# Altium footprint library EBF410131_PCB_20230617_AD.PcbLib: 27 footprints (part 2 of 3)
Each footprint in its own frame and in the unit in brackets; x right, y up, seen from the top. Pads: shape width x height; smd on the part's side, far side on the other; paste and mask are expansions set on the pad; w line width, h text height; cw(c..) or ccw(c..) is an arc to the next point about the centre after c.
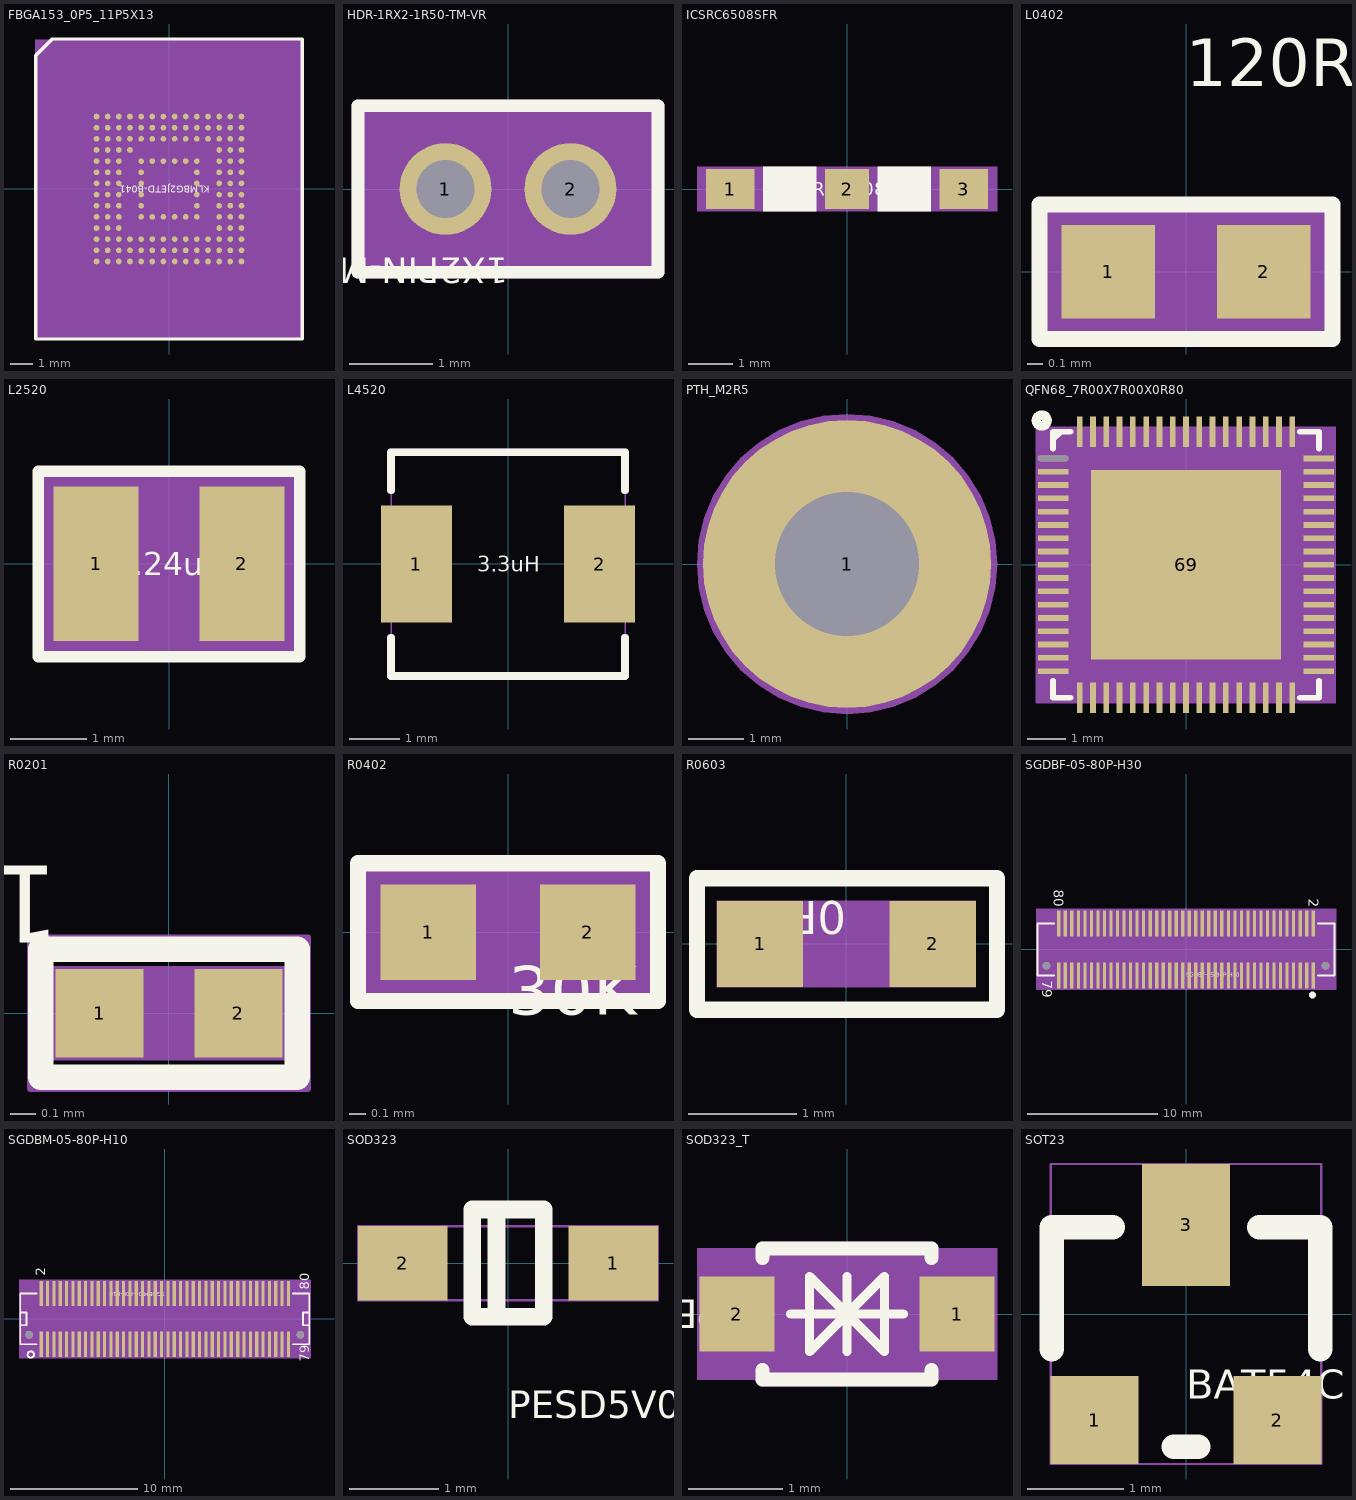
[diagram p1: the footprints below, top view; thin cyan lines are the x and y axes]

## FBGA153_0P5_11P5X13 [mil] "FBGA153_0P5_11P5X13"
pads (153):
  round 10 smd: A1(-127.95,127.95) A2(-108.27,127.95) A3(-88.58,127.95) A4(-68.9,127.95) A5(-49.21,127.95) A6(-29.53,127.95) A7(-9.84,127.95) A8(9.84,127.95) A9(29.53,127.95) A10(49.21,127.95) A11(68.9,127.95) A12(88.58,127.95) A13(108.27,127.95) A14(127.95,127.95) B1(-127.95,108.27) B2(-108.27,108.27) B3(-88.58,108.27) B4(-68.9,108.27) B5(-49.21,108.27) B6(-29.53,108.27) B7(-9.84,108.27) B8(9.84,108.27) B9(29.53,108.27) B10(49.21,108.27) B11(68.9,108.27) B12(88.58,108.27) B13(108.27,108.27) B14(127.95,108.27) C1(-127.95,88.58) C2(-108.27,88.58) C3(-88.58,88.58) C4(-68.9,88.58) C5(-49.21,88.58) C6(-29.53,88.58) C7(-9.84,88.58) C8(9.84,88.58) C9(29.53,88.58) C10(49.21,88.58) C11(68.9,88.58) C12(88.58,88.58) C13(108.27,88.58) C14(127.95,88.58) D1(-127.95,68.9) D2(-108.27,68.9) D3(-88.58,68.9) D4(-68.9,68.9) D12(88.58,68.9) D13(108.27,68.9) D14(127.95,68.9) E1(-127.95,49.21) E2(-108.27,49.21) E3(-88.58,49.21) E5(-49.21,49.21) E6(-29.53,49.21) E7(-9.84,49.21) E8(9.84,49.21) E9(29.53,49.21) E10(49.21,49.21) E12(88.58,49.21) E13(108.27,49.21) E14(127.95,49.21) F1(-127.95,29.53) F2(-108.27,29.53) F3(-88.58,29.53) F5(-49.21,29.53) F10(49.21,29.53) F12(88.58,29.53) F13(108.27,29.53) F14(127.95,29.53) G1(-127.95,9.84) G2(-108.27,9.84) G3(-88.58,9.84) G5(-49.21,9.84) G10(49.21,9.84) G12(88.58,9.84) G13(108.27,9.84) G14(127.95,9.84) H1(-127.95,-9.84) H2(-108.27,-9.84) H3(-88.58,-9.84) H5(-49.21,-9.84) H10(49.21,-9.84) H12(88.58,-9.84) H13(108.27,-9.84) H14(127.95,-9.84) J1(-127.95,-29.53) J2(-108.27,-29.53) J3(-88.58,-29.53) J5(-49.21,-29.53) J10(49.21,-29.53) J12(88.58,-29.53) J13(108.27,-29.53) J14(127.95,-29.53) K1(-127.95,-49.21) K2(-108.27,-49.21) K3(-88.58,-49.21) K5(-49.21,-49.21) K6(-29.53,-49.21) K7(-9.84,-49.21) K8(9.84,-49.21) K9(29.53,-49.21) K10(49.21,-49.21) K12(88.58,-49.21) K13(108.27,-49.21) K14(127.95,-49.21) L1(-127.95,-68.9) L2(-108.27,-68.9) L3(-88.58,-68.9) L12(88.58,-68.9) L13(108.27,-68.9) L14(127.95,-68.9) M1(-127.95,-88.58) M2(-108.27,-88.58) M3(-88.58,-88.58) M4(-68.9,-88.58) M5(-49.21,-88.58) M6(-29.53,-88.58) M7(-9.84,-88.58) M8(9.84,-88.58) M9(29.53,-88.58) M10(49.21,-88.58) M11(68.9,-88.58) M12(88.58,-88.58) M13(108.27,-88.58) M14(127.95,-88.58) N1(-127.95,-108.27) N2(-108.27,-108.27) N3(-88.58,-108.27) N4(-68.9,-108.27) N5(-49.21,-108.27) N6(-29.53,-108.27) N7(-9.84,-108.27) N8(9.84,-108.27) N9(29.53,-108.27) N10(49.21,-108.27) N11(68.9,-108.27) N12(88.58,-108.27) N13(108.27,-108.27) N14(127.95,-108.27) P1(-127.95,-127.95) P2(-108.27,-127.95) P3(-88.58,-127.95) P4(-68.9,-127.95) P5(-49.21,-127.95) P6(-29.53,-127.95) P7(-9.84,-127.95) P8(9.84,-127.95) P9(29.53,-127.95) P10(49.21,-127.95) P11(68.9,-127.95) P12(88.58,-127.95) P13(108.27,-127.95) P14(127.95,-127.95)
Top Overlay:
  lines w6: -235.35,-264.87 -235.35,235.77 -206.24,264.87 235.35,264.87 235.35,-264.87 -235.35,-264.87
  text "KLMBG2JETD-B041" at 72,6 h12
Top 3D Body:
  region: -236.22,-263.78 236.22,-263.78 236.22,263.78 -236.22,263.78
Top Component Center:
  lines w1: -10,0 10,0 ; 0,-10 0,10
Mechanical 12:
  text "E9" at 37.53,49.21 h10
  text "E10" at 61.21,49.21 h10
  text "F10" at 61.21,29.53 h10
  text "K10" at 61.21,-49.21 h10
  text "A1" at -119.95,127.95 h10
  text "A10" at 61.21,127.95 h10
  text "H2" at -100.27,-9.84 h10
  text "H3" at -80.58,-9.84 h10
  text "A11" at 80.9,127.95 h10
  text "H12" at 100.58,-9.84 h10
  text "H13" at 120.27,-9.84 h10
  text "H14" at 139.95,-9.84 h10
  text "J1" at -119.95,-29.53 h10
  text "J2" at -100.27,-29.53 h10
  text "J3" at -80.58,-29.53 h10
  text "A12" at 100.58,127.95 h10
  text "J12" at 100.58,-29.53 h10
  text "J13" at 120.27,-29.53 h10
  text "J14" at 139.95,-29.53 h10
  text "K1" at -119.95,-49.21 h10
  text "K2" at -100.27,-49.21 h10
  text "K3" at -80.58,-49.21 h10
  text "A13" at 120.27,127.95 h10
  text "K12" at 100.58,-49.21 h10
  text "K13" at 120.27,-49.21 h10
  text "A14" at 139.95,127.95 h10
  text "K14" at 139.95,-49.21 h10
  text "L1" at -119.95,-68.9 h10
  text "L2" at -100.27,-68.9 h10
  text "L3" at -80.58,-68.9 h10
  text "B1" at -119.95,108.27 h10
  text "L12" at 100.58,-68.9 h10
  text "L13" at 120.27,-68.9 h10
  text "L14" at 139.95,-68.9 h10
  text "M1" at -119.95,-88.58 h10
  text "M2" at -100.27,-88.58 h10
  text "M3" at -80.58,-88.58 h10
  text "M7" at -1.84,-88.58 h10
  text "M8" at 17.84,-88.58 h10
  text "M9" at 37.53,-88.58 h10
  text "M10" at 61.21,-88.58 h10
  text "M11" at 80.9,-88.58 h10
  text "M12" at 100.58,-88.58 h10
  text "M13" at 120.27,-88.58 h10
  text "M14" at 139.95,-88.58 h10
  text "N1" at -119.95,-108.27 h10
  text "N3" at -80.58,-108.27 h10
  text "N6" at -21.53,-108.27 h10
  text "N7" at -1.84,-108.27 h10
  text "N8" at 17.84,-108.27 h10
  text "N9" at 37.53,-108.27 h10
  text "N10" at 61.21,-108.27 h10
  text "N11" at 80.9,-108.27 h10
  text "N12" at 100.58,-108.27 h10
  text "N13" at 120.27,-108.27 h10
  text "N14" at 139.95,-108.27 h10
  text "P1" at -119.95,-127.95 h10
  text "P2" at -100.27,-127.95 h10
  text "P8" at 17.84,-127.95 h10
  text "P9" at 37.53,-127.95 h10
  text "P11" at 80.9,-127.95 h10
  text "P12" at 100.58,-127.95 h10
  text "P13" at 120.27,-127.95 h10
  text "P14" at 139.95,-127.95 h10
  text "A2" at -100.27,127.95 h10
  text "B7" at -1.84,108.27 h10
  text "B8" at 17.84,108.27 h10
  text "B9" at 37.53,108.27 h10
  text "B10" at 61.21,108.27 h10
  text "B11" at 80.9,108.27 h10
  text "B12" at 100.58,108.27 h10
  text "B13" at 120.27,108.27 h10
  text "B14" at 139.95,108.27 h10
  text "C1" at -119.95,88.58 h10
  text "C3" at -80.58,88.58 h10
  text "C5" at -41.21,88.58 h10
  text "C7" at -1.84,88.58 h10
  text "C8" at 17.84,88.58 h10
  text "C9" at 37.53,88.58 h10
  text "C10" at 61.21,88.58 h10
  text "C11" at 80.9,88.58 h10
  text "C12" at 100.58,88.58 h10
  text "C13" at 120.27,88.58 h10
  text "C14" at 139.95,88.58 h10
  text "D1" at -119.95,68.9 h10
  text "D2" at -100.27,68.9 h10
  text "D3" at -80.58,68.9 h10
  text "D4" at -60.9,68.9 h10
  text "D12" at 100.58,68.9 h10
  text "D13" at 120.27,68.9 h10
  text "D14" at 139.95,68.9 h10
  text "E1" at -119.95,49.21 h10
  text "E2" at -100.27,49.21 h10
  text "E3" at -80.58,49.21 h10
  text "E12" at 100.58,49.21 h10
  text "E13" at 120.27,49.21 h10
  text "E14" at 139.95,49.21 h10
  text "F1" at -119.95,29.53 h10
  text "F2" at -100.27,29.53 h10
  text "F3" at -80.58,29.53 h10
  text "A8" at 17.84,127.95 h10
  text "F12" at 100.58,29.53 h10
  text "F13" at 120.27,29.53 h10
  text "F14" at 139.95,29.53 h10
  text "G1" at -119.95,9.84 h10
  text "G2" at -100.27,9.84 h10
  text "A9" at 37.53,127.95 h10
  text "G12" at 100.58,9.84 h10
  text "G13" at 120.27,9.84 h10
  text "G14" at 139.95,9.84 h10
  text "H1" at -119.95,-9.84 h10
  text "A7" at -1.84,127.95 h10
  text "E5" at -41.21,49.21 h10
  text "E8" at 17.84,49.21 h10
  text "G3" at -80.58,9.84 h10
  text "G10" at 61.21,9.84 h10
  text "K6" at -21.53,-49.21 h10
  text "K7" at -1.84,-49.21 h10
  text "P7" at -1.84,-127.95 h10
  text "P10" at 61.21,-127.95 h10
  text "K5" at -41.21,-49.21 h10
  text "C2" at -100.27,88.58 h10
  text "M4" at -60.9,-88.58 h10
  text "N4" at -60.9,-108.27 h10
  text "P5" at -41.21,-127.95 h10
  text "P3" at -80.58,-127.95 h10
  text "C6" at -21.53,88.58 h10
  text "J10" at 61.21,-29.53 h10
  text "K9" at 37.53,-49.21 h10
  text "F5" at -41.21,29.53 h10
  text "E6" at -21.53,49.21 h10
  text "P4" at -60.9,-127.95 h10
  text "N5" at -41.21,-108.27 h10
  text "P6" at -21.53,-127.95 h10
  text "N2" at -100.27,-108.27 h10
  text "A6" at -21.53,127.95 h10
  text "K8" at 17.84,-49.21 h10
  text "H10" at 61.21,-9.84 h10
  text "E7" at -1.84,49.21 h10
  text "C4" at -60.9,88.58 h10
  text "J5" at -41.21,-29.53 h10
  text "G5" at -41.21,9.84 h10
  text "A3" at -80.58,127.95 h10
  text "A4" at -60.9,127.95 h10
  text "A5" at -41.21,127.95 h10
  text "B2" at -100.27,108.27 h10
  text "B3" at -80.58,108.27 h10
  text "B4" at -60.9,108.27 h10
  text "B5" at -41.21,108.27 h10
  text "B6" at -21.53,108.27 h10
  text "M5" at -41.21,-88.58 h10
  text "M6" at -21.53,-88.58 h10
  text "H5" at -41.21,-9.84 h10
Top Assembly:
  circle w6: c-188.98,220.47 r26.41
  lines w6: -228.35,-257.87 -228.35,232.87 -203.35,257.87 228.35,257.87 228.35,-257.87 -228.35,-257.87
3D body: height 150, standoff 0, extent -236.22,-263.78 236.22,263.78

## HDR-1RX2-1R50-TM-VR [mm] "HDR-1RX2-1R50-TM-VR"
pads (2):
  round 1.1 hole 0.7: 1(-0.75,0) 2(0.75,0)
Top Overlay:
  lines w0.15: -1.8,-1 -1.8,1 1.8,1 1.8,-1 -1.8,-1
  text "1X2PIN-M" at 0,-0.823 h0.3
Top 3D Body:
  region: -1.8,1 -1.8,-1 1.8,-1 1.8,1
Mechanical 12:
  text "2" at 0.75,-0.254 h0.64
  text "1" at -0.75,-0.254 h0.64
Top Assembly:
  lines w0.15: -1.8,-1 -0.8,-1 1.8,-1 1.8,1 -1.8,1 -1.8,-1
3D body: height 3.81, standoff 0, extent -1.8,-1 1.8,1

## ICSRC6508SFR [mm] "ICSRC6508SFR"
pads (3):
  rect 1.1x0.9 smd: 1(-2.65,0) 3(2.65,0)
  rect 1x0.9 smd: 2(0,0)
Top Overlay:
  dashed: -1.9,0.5 -1.9,-0.5 -0.7,-0.5 -0.7,0.5
  dashed: 0.7,0.5 0.7,-0.5 1.9,-0.5 1.9,0.5
  text "ICSRC6508SFR" at -1.463,-0.152 h0.3
Top 3D Body:
  region: 3.4,-0.5 3.4,0.5 -3.4,0.5 -3.4,-0.5
Mechanical 12:
  text "1" at -2.904,0 h0.64
  text "3" at 2.396,0 h0.64
  text "2" at -0.254,0 h0.64
Top Assembly:
  lines w0.1: -3.35,-0.45 3.35,-0.45 3.35,0.45 -3.35,0.45 -3.35,-0.45
3D body: height 3.81, standoff 0, extent -3.4,-0.5 3.4,0.5

## L0402 [mm] "L0402"
pads (2):
  rect 0.599x0.599 smd: 1(-0.5,0) 2(0.5,0)
Top Overlay:
  lines w0.102: -0.94,-0.432 -0.94,0.432 0.94,0.432 0.94,-0.432 -0.94,-0.432
  text "120R 100MHz" at 0,1.189 h0.3
Top 3D Body:
  region: 0.94,0.432 0.94,-0.432 -0.94,-0.432 -0.94,0.432
Mechanical 12:
  text "1" at -0.5,0.254 h0.64
  text "2" at 0.5,0.254 h0.64
Top Assembly:
  dashed: -0.94,-0.432 -0.94,0.432 0.94,0.432 0.94,-0.432
3D body: height 3.81, standoff 0, extent -0.94,-0.432 0.94,0.432

## L2520 [mil] "L2520"
pads (2):
  rect 44x80 smd: 1(-37.75,0) 2(37.75,0)
Top Overlay:
  lines w6: -67.68,-48.15 -67.68,47.92 67.67,47.92 67.67,-48.15 -67.67,-48.15 -67.68,-48.15
  text "0.24uH" at -28.8,-6 h12
Top 3D Body:
  region: -65,-45 65,-45 65,45 -65,45
Mechanical 12:
  text "1" at -42.47,0 h11.81
  text "2" at 33.02,0 h11.81
3D body: height 150, standoff 0, extent -65,-45 65,45

## L4520 [mm] "L4520"
pads (2):
  rect 1.4x2.3 smd: 1(-1.803,-0.003) 2(1.798,-0.003)
Top Overlay:
  lines w0.15: -2.303,-1.452 -2.303,-2.203 2.298,-2.203 2.298,-1.452 ; -2.303,1.447 -2.303,2.198 2.298,2.198 2.298,1.447
  text "3.3uH" at -0.61,-0.152 h0.3
Top 3D Body:
  lines w0.025: -2.303,-2.203 -2.303,2.202 2.303,2.202 2.303,-2.203 -2.303,-2.203
Mechanical 12:
  text "2" at 1.544,-0.003 h0.64
  text "1" at -2.057,-0.003 h0.64
Top Assembly:
  lines w0.15: -2.303,-1.452 -2.303,-2.203 2.298,-2.203 2.298,-1.452 ; -2.303,1.447 -2.303,2.198 2.298,2.198 2.298,1.447

## PTH_M2R5 [mm] "PTH_M2R5"
pads (1):
  round 5.2 hole 2.6: 1(0,0)
Top Overlay:
  text "PTH_M2.5" at -0.975,-0.152 h0.3
Top 3D Body:
  region: 2.708,0 2.675,0.424 2.576,0.837 2.413,1.23 2.191,1.592 1.915,1.915 1.592,2.191 1.23,2.413 0.837,2.576 0.424,2.675 0,2.708 -0.424,2.675 -0.837,2.576 -1.23,2.413 -1.35,2.339 -1.592,2.191 -1.915,1.915 -2.191,1.592 -2.413,1.23 -2.576,0.837 -2.675,0.424 -2.708,0 -2.675,-0.424 -2.576,-0.837 -2.413,-1.23 -2.191,-1.592 -1.915,-1.915 -1.592,-2.191 -1.35,-2.339 -1.23,-2.413 -0.837,-2.576 -0.424,-2.675 0,-2.708 0.424,-2.675 0.837,-2.576 1.23,-2.413 1.592,-2.191 1.915,-1.915 2.191,-1.592 2.413,-1.23 2.576,-0.837 2.675,-0.424
Mechanical 12:
  text "1" at -0.254,0 h0.64
3D body: height 3.81, standoff 0, extent -2.708,-2.708 2.708,2.708

## QFN68_7R00X7R00X0R80 [mil] "QFN68_7R00X7R00X0R80"
pads (69):
  oval 31.5x5.9 smd: 1(-137.8,110.24)
  rect 31.5x5.9 smd: 2(-137.8,96.46) 3(-137.8,82.68) 4(-137.8,68.9) 5(-137.8,55.12) 6(-137.8,41.34) 7(-137.8,27.56) 8(-137.8,13.78) 9(-137.8,0) 10(-137.8,-13.78) 11(-137.8,-27.56) 12(-137.8,-41.34) 13(-137.8,-55.12) 14(-137.8,-68.9) 15(-137.8,-82.68) 16(-137.8,-96.46) 17(-137.8,-110.24) 35(137.8,-110.24) 36(137.8,-96.46) 37(137.8,-82.68) 38(137.8,-68.9) 39(137.8,-55.12) 40(137.8,-41.34) 41(137.8,-27.56) 42(137.8,-13.78) 43(137.8,0) 44(137.8,13.78) 45(137.8,27.56) 46(137.8,41.34) 47(137.8,55.12) 48(137.8,68.9) 49(137.8,82.68) 50(137.8,96.46) 51(137.8,110.24)
  rect 5.9x31.5 smd: 18(-110.24,-137.8) 19(-96.46,-137.8) 20(-82.68,-137.8) 21(-68.9,-137.8) 22(-55.12,-137.8) 23(-41.34,-137.8) 24(-27.56,-137.8) 25(-13.78,-137.8) 26(0,-137.8) 27(13.78,-137.8) 28(27.56,-137.8) 29(41.34,-137.8) 30(55.12,-137.8) 31(68.9,-137.8) 32(82.68,-137.8) 33(96.46,-137.8) 34(110.24,-137.8) 52(110.24,137.8) 53(96.46,137.8) 54(82.68,137.8) 55(68.9,137.8) 56(55.12,137.8) 57(41.34,137.8) 58(27.56,137.8) 59(13.78,137.8) 60(0,137.8) 61(-13.78,137.8) 62(-27.56,137.8) 63(-41.34,137.8) 64(-55.12,137.8) 65(-68.9,137.8) 66(-82.68,137.8) 67(-96.46,137.8) 68(-110.24,137.8)
  rect 196.85x196.85 smd: 69(0,0)
Top Overlay:
  circle w9.84: c-149.61,149.61 r5.57
  lines w5.91: -137.8,-120.08 -137.8,-137.8 -119.69,-137.8 ; -137.8,120.47 -137.8,137.8 -119.69,137.8 ; -137.8,129.92 -129.92,137.8 ; 118.11,-137.8 137.8,-137.8 137.8,-120.08 ; 118.11,137.8 137.8,137.8 137.8,120.47
  text "RK809-5" at -0.01,27.6 h12
Top 3D Body:
  region: -155.51,-142.91 155.51,-142.91 155.51,142.91 -155.51,142.91
Mechanical 12:
  text "51" at 137.8,130.24 h25
  text "65" at -68.9,157.8 h25
  text "50" at 137.8,116.46 h25
  text "25" at -13.78,-117.8 h25
  text "1" at -137.8,120.24 h25
  text "45" at 137.8,47.56 h25
  text "2" at -137.8,106.46 h25
  text "34" at 110.24,-117.8 h25
  text "32" at 82.68,-117.8 h25
  text "27" at 13.78,-117.8 h25
  text "52" at 110.24,157.8 h25
  text "33" at 96.46,-117.8 h25
  text "36" at 137.8,-76.46 h25
  text "37" at 137.8,-62.68 h25
  text "38" at 137.8,-48.9 h25
  text "60" at 0,157.8 h25
  text "35" at 137.8,-90.24 h25
  text "48" at 137.8,88.9 h25
  text "44" at 137.8,33.78 h25
  text "53" at 96.46,157.8 h25
  text "16" at -137.8,-76.46 h25
  text "15" at -137.8,-62.68 h25
  text "14" at -137.8,-48.9 h25
  text "17" at -137.8,-90.24 h25
  text "19" at -96.46,-117.8 h25
  text "49" at 137.8,102.68 h25
  text "7" at -137.8,37.56 h25
  text "43" at 137.8,20 h25
  text "42" at 137.8,6.22 h25
  text "59" at 13.78,157.8 h25
  text "55" at 68.9,157.8 h25
  text "67" at -96.46,157.8 h25
  text "63" at -41.34,157.8 h25
  text "69" at 0,20 h25
  text "62" at -27.56,157.8 h25
  text "47" at 137.8,75.12 h25
  text "56" at 55.12,157.8 h25
  text "3" at -137.8,92.68 h25
  text "8" at -137.8,23.78 h25
  text "64" at -55.12,157.8 h25
  text "58" at 27.56,157.8 h25
  text "6" at -137.8,51.34 h25
  text "5" at -137.8,65.12 h25
  text "31" at 68.9,-117.8 h25
  text "12" at -137.8,-21.34 h25
  text "29" at 41.34,-117.8 h25
  text "28" at 27.56,-117.8 h25
  text "20" at -82.68,-117.8 h25
  text "21" at -68.9,-117.8 h25
  text "23" at -41.34,-117.8 h25
  text "30" at 55.12,-117.8 h25
  text "24" at -27.56,-117.8 h25
  text "22" at -55.12,-117.8 h25
  text "11" at -137.8,-7.56 h25
  text "10" at -137.8,6.22 h25
  text "54" at 82.68,157.8 h25
  text "4" at -137.8,78.9 h25
  text "66" at -82.68,157.8 h25
  text "57" at 41.34,157.8 h25
  text "18" at -110.24,-117.8 h25
  text "46" at 137.8,61.34 h25
  text "39" at 137.8,-35.12 h25
  text "41" at 137.8,-7.56 h25
  text "40" at 137.8,-21.34 h25
  text "61" at -13.78,157.8 h25
  text "26" at 0,-117.8 h25
  text "68" at -110.24,157.8 h25
  text "13" at -137.8,-35.12 h25
  text "9" at -137.8,10 h25
Top Assembly:
  lines w1: -155.51,-142.91 -155.51,142.91 155.51,142.91 155.51,-142.91 -155.51,-142.91
  text ".Designator" at 0,9 h30
3D body: height 150, standoff 0, extent -155.51,-142.91 155.51,142.91

## R0201 [mm] "R0201"
pads (2):
  rect 0.35x0.35 smd: 1(-0.275,0) 2(0.275,0)
Top Overlay:
  lines w0.102: -0.508,-0.254 -0.508,0.254 0.508,0.254 0.508,-0.254 -0.508,-0.254
  text "1.62K" at -0.431,0.583 h0.3
Top 3D Body:
  region: -0.475,-0.175 -0.475,0.175 0.475,0.175 0.475,-0.175
Mechanical 12:
  text "2" at 0.052,0.223 h0.79
  text "1" at -0.498,0.223 h0.79
Top Assembly:
  lines w0.025: -0.55,-0.3 0.55,-0.3 0.55,0.3 -0.55,0.3 -0.55,-0.3 ; -0.475,-0.175 0.475,-0.175 0.475,0.175 -0.475,0.175 -0.475,-0.175
  text "1.62K" at 0,0 h0.79
  text ".Designator" at -0.647,0.266 h0.76
3D body: height 3.81, standoff 0, extent -0.475,-0.175 0.475,0.175

## R0402 [mm] "R0402"
pads (2):
  rect 0.599x0.599 smd: 1(-0.5,0) 2(0.5,0)
Top Overlay:
  lines w0.102: -0.94,-0.432 -0.94,0.432 0.94,0.432 0.94,-0.432 -0.94,-0.432
  text "30K" at 0,-0.518 h0.3
Top 3D Body:
  region: 0.94,0.432 0.94,-0.432 -0.94,-0.432 -0.94,0.432
Mechanical 12:
  text "2" at 0.5,-0.254 h0.64
  text "1" at -0.5,-0.254 h0.64
Top Assembly:
  dashed: -0.94,-0.432 -0.94,0.432 0.94,0.432 0.94,-0.432
3D body: height 3.81, standoff 0, extent -0.94,-0.432 0.94,0.432

## R0603 [mil] "R0603"
pads (2):
  rect 31.5x31.5 smd: 1(-31.5,0) 2(31.5,0)
Top Overlay:
  lines w6: -54.5,-24 -54.5,24 55,24 55,-24 -54.5,-24
  text "0R" at -0.01,15.6 h12
Top 3D Body:
  region: -47.24,-15.75 -47.24,15.75 47.24,15.75 47.24,-15.75
Mechanical 12:
  text "2" at 31.5,18 h45
  text "1" at -31.5,18 h45
3D body: height 150, standoff 0, extent -47.24,-15.75 47.24,15.75

## SGDBF-05-80P-H30 [mm] "SGDBF-05-80P-H30"
pads (82):
  rect 0.25x2 smd: 1(9.75,-2) 2(9.75,2) 3(9.25,-2) 4(9.25,2) 5(8.75,-2) 6(8.75,2) 7(8.25,-2) 8(8.25,2) 9(7.75,-2) 10(7.75,2) 11(7.25,-2) 12(7.25,2) 13(6.75,-2) 14(6.75,2) 15(6.25,-2) 16(6.25,2) 17(5.75,-2) 18(5.75,2) 19(5.25,-2) 20(5.25,2) 21(4.75,-2) 22(4.75,2) 23(4.25,-2) 24(4.25,2) 25(3.75,-2) 26(3.75,2) 27(3.25,-2) 28(3.25,2) 29(2.75,-2) 30(2.75,2) 31(2.25,-2) 32(2.25,2) 33(1.75,-2) 34(1.75,2) 35(1.25,-2) 36(1.25,2) 37(0.75,-2) 38(0.75,2) 39(0.25,-2) 40(0.25,2) 41(-0.25,-2) 42(-0.25,2) 43(-0.75,-2) 44(-0.75,2) 45(-1.25,-2) 46(-1.25,2) 47(-1.75,-2) 48(-1.75,2) 49(-2.25,-2) 50(-2.25,2) 51(-2.75,-2) 52(-2.75,2) 53(-3.25,-2) 54(-3.25,2) 55(-3.75,-2) 56(-3.75,2) 57(-4.25,-2) 58(-4.25,2) 59(-4.75,-2) 60(-4.75,2) 61(-5.25,-2) 62(-5.25,2) 63(-5.75,-2) 64(-5.75,2) 65(-6.25,-2) 66(-6.25,2) 67(-6.75,-2) 68(-6.75,2) 69(-7.25,-2) 70(-7.25,2) 71(-7.75,-2) 72(-7.75,2) 73(-8.25,-2) 74(-8.25,2) 75(-8.75,-2) 76(-8.75,2) 77(-9.25,-2) 78(-9.25,2) 79(-9.75,-2) 80(-9.75,2)
  round 0.6 hole 0.6 unplated: ""(-10.7,-1.25) ""(10.7,-1.25)
Top Overlay:
  dashed: 9.7,-3.245 9.798,-3.265 9.88,-3.32 9.935,-3.402 9.955,-3.5 9.935,-3.598 9.917,-3.625 9.88,-3.68 9.798,-3.735 9.7,-3.755 9.602,-3.735 9.52,-3.68 9.483,-3.625 9.465,-3.598 9.445,-3.5 9.465,-3.402 9.52,-3.32 9.602,-3.265
  lines w0.15: -10.1,-2 -11.4,-2 -11.4,2 -10.1,2 ; 10.1,-2 11.4,-2 11.4,2 10.1,2
  text "79" at -11.023,-2.4 h0.76
  text "2" at 9.424,3.874 h0.76
  text "80" at -10.134,4.585 h0.76
  text "SGDBF-05-80P-H30" at 0,-2.103 h0.3
Top 3D Body:
  region: 11.5,-3.1 11.5,3.1 -11.5,3.1 -11.5,-3.1
Mechanical 12:
  text "74" at -8.25,1.492 h0.64
  text "76" at -8.75,1.492 h0.64
  text "4" at 9.25,1.746 h0.64
  text "6" at 8.75,1.746 h0.64
  text "10" at 7.75,1.492 h0.64
  text "63" at -5.75,-2.508 h0.64
  text "61" at -5.25,-2.508 h0.64
  text "57" at -4.25,-2.508 h0.64
  text "12" at 7.25,1.492 h0.64
  text "45" at -1.25,-2.508 h0.64
  text "16" at 6.25,1.492 h0.64
  text "17" at 5.75,-2.508 h0.64
  text "43" at -0.75,-2.508 h0.64
  text "51" at -2.75,-2.508 h0.64
  text "34" at 1.75,1.492 h0.64
  text "32" at 2.25,1.492 h0.64
  text "49" at -2.25,-2.508 h0.64
  text "47" at -1.75,-2.508 h0.64
  text "53" at -3.25,-2.508 h0.64
  text "33" at 1.75,-2.508 h0.64
  text "67" at -6.75,-2.508 h0.64
  text "39" at 0.25,-2.508 h0.64
  text "35" at 1.25,-2.508 h0.64
  text "65" at -6.25,-2.508 h0.64
  text "37" at 0.75,-2.508 h0.64
  text "31" at 2.25,-2.508 h0.64
  text "59" at -4.75,-2.508 h0.64
  text "29" at 2.75,-2.508 h0.64
  text "3" at 9.25,-2.254 h0.64
  text "5" at 8.75,-2.254 h0.64
  text "77" at -9.25,-2.508 h0.64
  text "73" at -8.25,-2.508 h0.64
  text "71" at -7.75,-2.508 h0.64
  text "38" at 0.75,1.492 h0.64
  text "36" at 1.25,1.492 h0.64
  text "42" at -0.25,1.492 h0.64
  text "44" at -0.75,1.492 h0.64
  text "46" at -1.25,1.492 h0.64
  text "48" at -1.75,1.492 h0.64
  text "19" at 5.25,-2.508 h0.64
  text "20" at 5.25,1.492 h0.64
  text "50" at -2.25,1.492 h0.64
  text "21" at 4.75,-2.508 h0.64
  text "52" at -2.75,1.492 h0.64
  text "23" at 4.25,-2.508 h0.64
  text "54" at -3.25,1.492 h0.64
  text "25" at 3.75,-2.508 h0.64
  text "56" at -3.75,1.492 h0.64
  text "15" at 6.25,-2.508 h0.64
  text "70" at -7.25,1.492 h0.64
  text "13" at 6.75,-2.508 h0.64
  text "72" at -7.75,1.492 h0.64
  text "18" at 5.75,1.492 h0.64
  text "60" at -4.75,1.492 h0.64
  text "62" at -5.25,1.492 h0.64
  text "7" at 8.25,-2.254 h0.64
  text "9" at 7.75,-2.254 h0.64
  text "80" at -9.75,1.492 h0.64
  text "78" at -9.25,1.492 h0.64
  text "1" at 9.75,-2.254 h0.64
  text "11" at 7.25,-2.508 h0.64
  text "27" at 3.25,-2.508 h0.64
  text "41" at -0.25,-2.508 h0.64
  text "55" at -3.75,-2.508 h0.64
  text "69" at -7.25,-2.508 h0.64
  text "75" at -8.75,-2.508 h0.64
  text "79" at -9.75,-2.508 h0.64
  text "2" at 9.75,1.746 h0.64
  text "8" at 8.25,1.746 h0.64
  text "14" at 6.75,1.492 h0.64
  text "30" at 2.75,1.492 h0.64
  text "40" at 0.25,1.492 h0.64
  text "58" at -4.25,1.492 h0.64
  text "64" at -5.75,1.492 h0.64
  text "68" at -6.75,1.492 h0.64
  text "66" at -6.25,1.492 h0.64
  text "22" at 4.75,1.492 h0.64
  text "24" at 4.25,1.492 h0.64
  text "26" at 3.75,1.492 h0.64
  text "28" at 3.25,1.492 h0.64
Top Assembly:
  lines w0.15: -11.4,-2 -11.4,2 11.4,2 11.4,-2 -11.4,-2
3D body: height 3.81, standoff 0, extent -11.5,-3.1 11.5,3.1

## SGDBM-05-80P-H10 [mm] "SGDBM-05-80P-H10"
pads (82):
  rect 0.25x2 smd: 1(-9.75,-2) 2(-9.75,2) 3(-9.25,-2) 4(-9.25,2) 5(-8.75,-2) 6(-8.75,2) 7(-8.25,-2) 8(-8.25,2) 9(-7.75,-2) 10(-7.75,2) 11(-7.25,-2) 12(-7.25,2) 13(-6.75,-2) 14(-6.75,2) 15(-6.25,-2) 16(-6.25,2) 17(-5.75,-2) 18(-5.75,2) 19(-5.25,-2) 20(-5.25,2) 21(-4.75,-2) 22(-4.75,2) 23(-4.25,-2) 24(-4.25,2) 25(-3.75,-2) 26(-3.75,2) 27(-3.25,-2) 28(-3.25,2) 29(-2.75,-2) 30(-2.75,2) 31(-2.25,-2) 32(-2.25,2) 33(-1.75,-2) 34(-1.75,2) 35(-1.25,-2) 36(-1.25,2) 37(-0.75,-2) 38(-0.75,2) 39(-0.25,-2) 40(-0.25,2) 41(0.25,-2) 42(0.25,2) 43(0.75,-2) 44(0.75,2) 45(1.25,-2) 46(1.25,2) 47(1.75,-2) 48(1.75,2) 49(2.25,-2) 50(2.25,2) 51(2.75,-2) 52(2.75,2) 53(3.25,-2) 54(3.25,2) 55(3.75,-2) 56(3.75,2) 57(4.25,-2) 58(4.25,2) 59(4.75,-2) 60(4.75,2) 61(5.25,-2) 62(5.25,2) 63(5.75,-2) 64(5.75,2) 65(6.25,-2) 66(6.25,2) 67(6.75,-2) 68(6.75,2) 69(7.25,-2) 70(7.25,2) 71(7.75,-2) 72(7.75,2) 73(8.25,-2) 74(8.25,2) 75(8.75,-2) 76(8.75,2) 77(9.25,-2) 78(9.25,2) 79(9.75,-2) 80(9.75,2)
  round 0.6 hole 0.6 unplated: ""(-10.7,-1.25) ""(10.7,-1.25)
Top Overlay:
  circle w0.15: c-10.567,-2.815 r0.25
  lines w0.15: -11.4,0 -11.4,-0.5 -10.9,-0.5 -10.9,0.5 -11.4,0.5 ; -10.1,-2 -11.4,-2 -11.4,2 -10.1,2 ; 10.1,-2 11.4,-2 11.4,2 10.1,2 ; 11.4,0 11.4,-0.5 10.9,-0.5 10.9,0.5 11.4,0.5
  text "80" at 11.404,2.316 h0.76
  text "79" at 11.404,-3.399 h0.76
  text "2" at -9.424,3.408 h0.76
  text "SGDBM-05-80P-H10" at 0,2.103 h0.3
Top 3D Body:
  region: -11.5,3.1 -11.5,-3.1 11.5,-3.1 11.5,3.1
Mechanical 12:
  text "8" at -8.25,2.254 h0.64
  text "10" at -7.75,2.508 h0.64
  text "17" at -5.75,-1.492 h0.64
  text "15" at -6.25,-1.492 h0.64
  text "25" at -3.75,-1.492 h0.64
  text "27" at -3.25,-1.492 h0.64
  text "11" at -7.25,-1.492 h0.64
  text "14" at -6.75,2.508 h0.64
  text "16" at -6.25,2.508 h0.64
  text "13" at -6.75,-1.492 h0.64
  text "18" at -5.75,2.508 h0.64
  text "20" at -5.25,2.508 h0.64
  text "22" at -4.75,2.508 h0.64
  text "24" at -4.25,2.508 h0.64
  text "19" at -5.25,-1.492 h0.64
  text "21" at -4.75,-1.492 h0.64
  text "9" at -7.75,-1.746 h0.64
  text "7" at -8.25,-1.746 h0.64
  text "48" at 1.75,2.508 h0.64
  text "46" at 1.25,2.508 h0.64
  text "3" at -9.25,-1.746 h0.64
  text "44" at 0.75,2.508 h0.64
  text "5" at -8.75,-1.746 h0.64
  text "34" at -1.75,2.508 h0.64
  text "28" at -3.25,2.508 h0.64
  text "36" at -1.25,2.508 h0.64
  text "72" at 7.75,2.508 h0.64
  text "74" at 8.25,2.508 h0.64
  text "30" at -2.75,2.508 h0.64
  text "66" at 6.25,2.508 h0.64
  text "68" at 6.75,2.508 h0.64
  text "52" at 2.75,2.508 h0.64
  text "50" at 2.25,2.508 h0.64
  text "42" at 0.25,2.508 h0.64
  text "37" at -0.75,-1.492 h0.64
  text "39" at -0.25,-1.492 h0.64
  text "32" at -2.25,2.508 h0.64
  text "43" at 0.75,-1.492 h0.64
  text "41" at 0.25,-1.492 h0.64
  text "38" at -0.75,2.508 h0.64
  text "45" at 1.25,-1.492 h0.64
  text "31" at -2.25,-1.492 h0.64
  text "29" at -2.75,-1.492 h0.64
  text "62" at 5.25,2.508 h0.64
  text "60" at 4.75,2.508 h0.64
  text "26" at -3.75,2.508 h0.64
  text "1" at -9.75,-1.746 h0.64
  text "2" at -9.75,2.254 h0.64
  text "80" at 9.75,2.508 h0.64
  text "79" at 9.75,-1.492 h0.64
  text "71" at 7.75,-1.492 h0.64
  text "73" at 8.25,-1.492 h0.64
  text "78" at 9.25,2.508 h0.64
  text "77" at 9.25,-1.492 h0.64
  text "64" at 5.75,2.508 h0.64
  text "70" at 7.25,2.508 h0.64
  text "69" at 7.25,-1.492 h0.64
  text "33" at -1.75,-1.492 h0.64
  text "23" at -4.25,-1.492 h0.64
  text "58" at 4.25,2.508 h0.64
  text "54" at 3.25,2.508 h0.64
  text "40" at -0.25,2.508 h0.64
  text "12" at -7.25,2.508 h0.64
  text "75" at 8.75,-1.492 h0.64
  text "76" at 8.75,2.508 h0.64
  text "56" at 3.75,2.508 h0.64
  text "51" at 2.75,-1.492 h0.64
  text "55" at 3.75,-1.492 h0.64
  text "67" at 6.75,-1.492 h0.64
  text "49" at 2.25,-1.492 h0.64
  text "57" at 4.25,-1.492 h0.64
  text "61" at 5.25,-1.492 h0.64
  text "63" at 5.75,-1.492 h0.64
  text "59" at 4.75,-1.492 h0.64
  text "65" at 6.25,-1.492 h0.64
  text "47" at 1.75,-1.492 h0.64
  text "53" at 3.25,-1.492 h0.64
  text "4" at -9.25,2.254 h0.64
  text "6" at -8.75,2.254 h0.64
  text "35" at -1.25,-1.492 h0.64
Top Assembly:
  lines w0.15: -11.4,-2 -11.4,2 11.4,2 11.4,-2 -11.4,-2
3D body: height 3.81, standoff 0, extent -11.5,-3.1 11.5,3.1

## SOD323 [mm] "SOD323"
pads (2):
  rect 1x0.83 smd: 1(1.18,0) 2(-1.18,0)
Top Overlay:
  lines w0.2: -0.13,-0.6 -0.13,0.6 ; -0.4,-0.6 0.4,-0.6 0.4,0.6 -0.4,0.6 -0.4,-0.6
  text "PESD5V0S1BA-N" at 0,-1.737 h0.3
Top 3D Body:
  lines w0.025: -1.68,-0.415 1.68,-0.415 1.68,0.415 -1.68,0.415 -1.68,-0.415
Mechanical 12:
  text "1" at 1.18,-0.122 h0.3
  text "2" at -1.18,-0.122 h0.3

## SOD323_T [mm] "SOD323_T"
pads (2):
  rect 0.8x0.8 smd: 1(1.175,0) 2(-1.175,0)
Top Overlay:
  lines w0.1: -0.6,0 0.6,0 ; 0,-0.4 0,0.4 ; 0,0 -0.4,0.4 -0.4,-0.4 0,0 ; 0,0 0.4,-0.4 0.4,0.4 0,0
  lines w0.15: -0.9,-0.6 -0.9,-0.7 0.9,-0.7 0.9,-0.6 ; -0.9,0.6 -0.9,0.7 0.9,0.7 0.9,0.6
  text "PESD3V3L1BA" at -1.341,0.152 h0.3
Top 3D Body:
  region: 1.6,-0.7 1.6,0.7 -1.6,0.7 -1.6,-0.7
Mechanical 12:
  text "1" at 0.921,0 h0.64
  text "2" at -1.429,0 h0.64
Top Assembly:
  lines w0.15: -0.9,-0.7 -0.9,0.7 0.9,0.7 0.9,-0.7 -0.9,-0.7
3D body: height 3.81, standoff 0, extent -1.6,-0.7 1.6,0.7

## SOT23 [mil] "SOT23"
pads (3):
  rect 36x36 smd: 1(-37.5,-43.5) 2(37.5,-43.5)
  rect 36x50 smd: 3(0,36.5)
Top Overlay:
  lines w10: -55,-14.5 -55,35.5 -30,35.5 ; -5,-54.5 5,-54.5 ; 30,35.5 55,35.5 55,-14.5
  text "BAT54C" at 0.01,-34.8 h12
Top 3D Body:
  lines w1: -55.5,-61.5 55.5,-61.5 55.5,61.5 -55.5,61.5 -55.5,-61.5
Mechanical 12:
  text "3" at 0,18.5 h45
  text "1" at -37.5,-61.5 h45
  text "2" at 37.5,-61.5 h45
